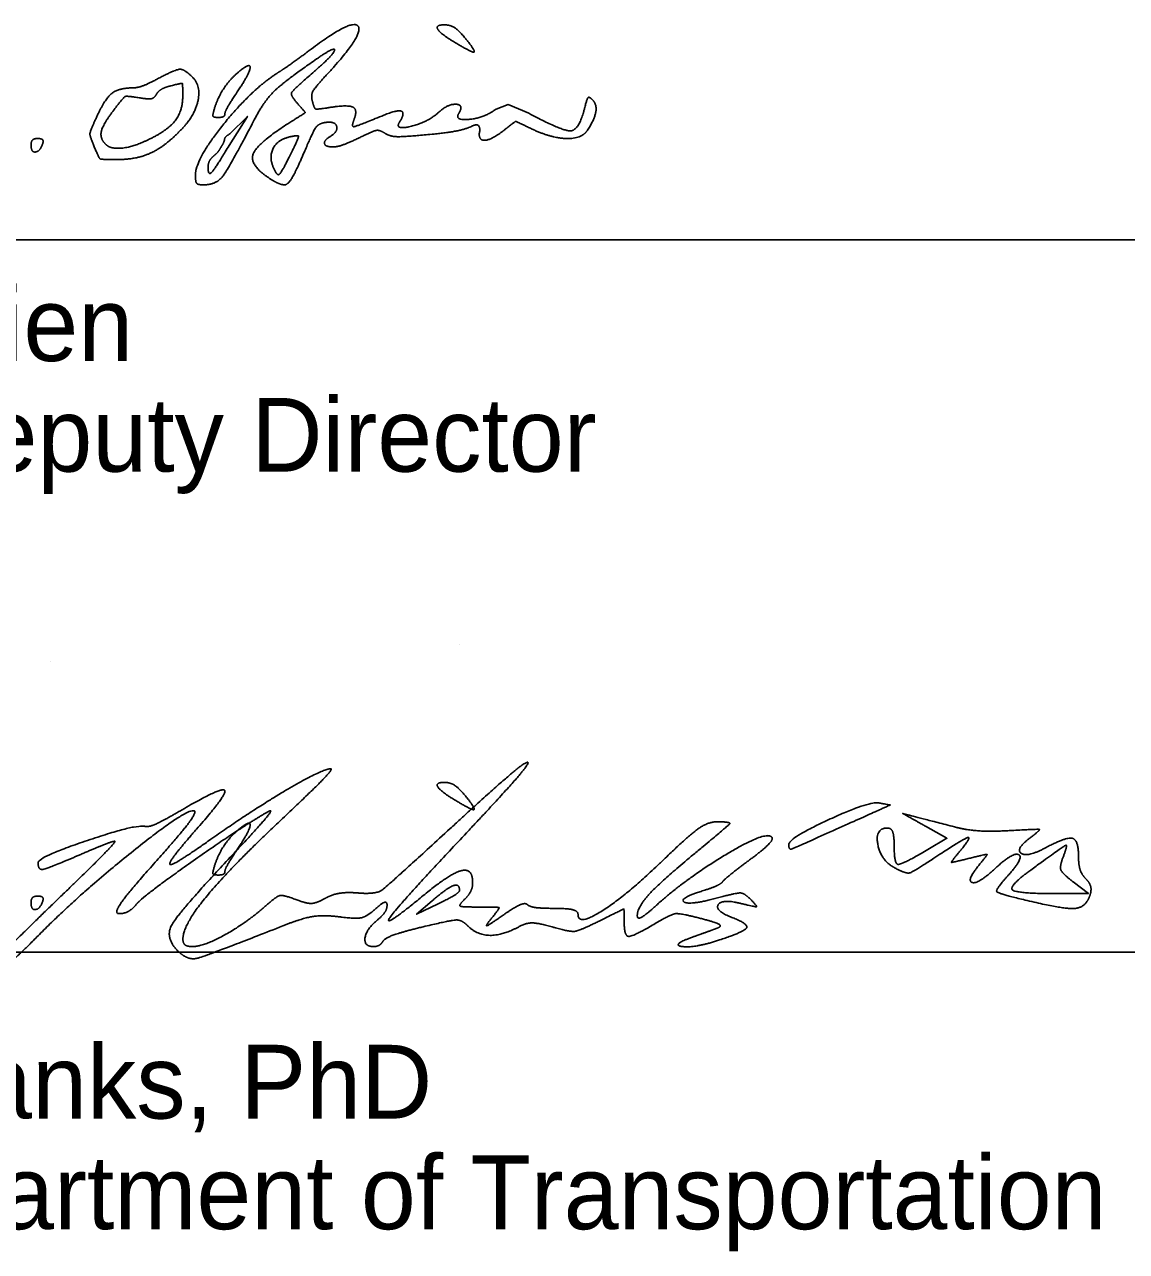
# Model space of a CAD drawing. Extents: x 0 to 34, y 0 to 22.
# Drawn here: x 25.679 to 27.771, y 6.366 to 8.695 of the extents above; entities that cross this region are included whole.
import ezdxf

# ---------------------------------------------------------------- set-up
doc = ezdxf.new("R2010")
doc.units = 0
doc.layers.add('SH_Data', color=7, linetype='Continuous')
doc.layers.add('SH_Text', color=7, linetype='Continuous')

msp = doc.modelspace()

# ---------------------------------------------------------------- linework, layer by layer
at = {"layer": 'SH_Data'}
for p, q in [((24.5279, 8.2866), (28.0279, 8.2866)), ((24.5279, 6.9345), (28.0279, 6.9345))]:
    msp.add_line(p, q, dxfattribs=at)
at = {"layer": 'SH_Text'}
for p, q in [((26.4932, 8.6629), (26.4932, 8.6629)), ((26.5045, 7.5178), (26.5045, 7.5178)), ((25.7273, 7.4868), (25.7273, 7.4868)), ((26.4932, 7.2248), (26.4932, 7.2248)), ((27.1295, 7.1387), (27.1295, 7.1387)), ((27.582, 7.0325), (27.582, 7.0325))]:
    msp.add_line(p, q, dxfattribs=at)
for points in [[(26.636, 8.5269), (26.597, 8.5435), (26.574, 8.535)], [(26.0685, 8.4876), (26.1019, 8.5208), (26.0672, 8.4659)], [(27.3933, 7.1291), (27.4297, 7.1506), (27.3889, 7.1736)], [(27.642, 7.0456), (27.6982, 7.0457), (27.6695, 7.0678)], [(26.4527, 7.032), (26.4232, 7.0064), (26.4638, 7.0261)]]:
    msp.add_lwpolyline(points, dxfattribs=at)
for points in [[(26.2529, 8.6006), (26.3225, 8.6754), (26.3023, 8.7082), (26.2232, 8.6489)], [(26.4932, 8.6629), (26.467, 8.6789), (26.4588, 8.6952), (26.4772, 8.6947)], [(26.4772, 8.6947), (26.4887, 8.6944), (26.5064, 8.6812), (26.5222, 8.661)], [(26.2232, 8.6489), (26.2012, 8.6324), (26.1724, 8.6119), (26.1592, 8.6035)], [(26.2332, 8.63), (26.2688, 8.6547), (26.2661, 8.6386), (26.2292, 8.6066)], [(26.5222, 8.661), (26.5367, 8.6425), (26.5254, 8.6433), (26.4932, 8.6629)], [(26.0861, 8.6061), (26.1081, 8.6243), (26.1061, 8.6024), (26.0827, 8.5674)], [(26.1167, 8.5177), (26.1337, 8.5504), (26.1732, 8.5884), (26.2332, 8.63)], [(25.9977, 8.5954), (25.982, 8.6111), (25.9646, 8.6099), (25.9291, 8.591)], [(25.9786, 8.4983), (26.0029, 8.5241), (26.0137, 8.5794), (25.9977, 8.5954)], [(26.1592, 8.6035), (26.1093, 8.5715), (26.0032, 8.4396), (26.0032, 8.4095)], [(26.0397, 8.537), (26.0462, 8.5577), (26.0692, 8.592), (26.0861, 8.6061)], [(26.2292, 8.6066), (26.1879, 8.5707), (26.1832, 8.5607), (26.1992, 8.543)], [(26.2252, 8.5497), (26.2222, 8.5614), (26.2302, 8.5761), (26.2529, 8.6006)], [(25.883, 8.575), (25.857, 8.575), (25.8307, 8.5532), (25.8153, 8.5191)], [(25.9291, 8.591), (25.9127, 8.5822), (25.892, 8.575), (25.883, 8.575)], [(25.9291, 8.5628), (25.9325, 8.5688), (25.9451, 8.5762), (25.9572, 8.5792)], [(25.9572, 8.5792), (25.9776, 8.5843), (25.9792, 8.5829), (25.9792, 8.5604)], [(25.8483, 8.5331), (25.8668, 8.5573), (25.8727, 8.5602), (25.8962, 8.5564)], [(25.8962, 8.5564), (25.9142, 8.5534), (25.925, 8.5556), (25.9291, 8.5628)], [(25.9792, 8.5604), (25.9792, 8.5309), (25.9497, 8.4937), (25.9121, 8.4759)], [(26.0827, 8.5674), (26.0698, 8.5483), (26.0592, 8.5295), (26.0592, 8.5258)], [(26.2584, 8.5379), (26.2339, 8.534), (26.2289, 8.5358), (26.2252, 8.5497)], [(26.7567, 8.5527), (26.7506, 8.5588), (26.7465, 8.5546), (26.7424, 8.5381)], [(26.7476, 8.495), (26.7612, 8.5159), (26.7656, 8.5438), (26.7567, 8.5527)], [(25.8326, 8.4683), (25.8214, 8.4794), (25.828, 8.5065), (25.8483, 8.5331)], [(26.0467, 8.519), (26.0374, 8.519), (26.0356, 8.5236), (26.0397, 8.537)], [(26.0592, 8.5258), (26.0592, 8.522), (26.0536, 8.519), (26.0467, 8.519)], [(26.1992, 8.543), (26.2118, 8.529), (26.2113, 8.5274), (26.1899, 8.5141)], [(26.3044, 8.5152), (26.3116, 8.5339), (26.2926, 8.5433), (26.2584, 8.5379)], [(26.3905, 8.5099), (26.4015, 8.5275), (26.3872, 8.5341), (26.3611, 8.5234)], [(26.4648, 8.5286), (26.4453, 8.5105), (26.3809, 8.4942), (26.3905, 8.5099)], [(26.5033, 8.527), (26.5134, 8.5434), (26.4821, 8.5447), (26.4648, 8.5286)], [(26.574, 8.535), (26.5525, 8.5185), (26.4941, 8.5122), (26.5033, 8.527)], [(26.7424, 8.5381), (26.7319, 8.4953), (26.7008, 8.492), (26.636, 8.5269)], [(25.8153, 8.5191), (25.8032, 8.4922), (25.8026, 8.4839), (25.8111, 8.4632)], [(26.0178, 8.391), (26.0424, 8.391), (26.0675, 8.4232), (26.1167, 8.5177)], [(26.1899, 8.5141), (26.1224, 8.4722), (26.1042, 8.4293), (26.143, 8.4039)], [(26.208, 8.4491), (26.2265, 8.4924), (26.2371, 8.5076), (26.25, 8.5095)], [(26.25, 8.5095), (26.2679, 8.5122), (26.2747, 8.4925), (26.2592, 8.483)], [(26.3611, 8.5234), (26.3092, 8.5022), (26.2989, 8.5007), (26.3044, 8.5152)], [(26.4563, 8.4875), (26.5084, 8.4924), (26.5469, 8.5119), (26.5419, 8.487)], [(26.59, 8.4954), (26.6104, 8.5115), (26.6116, 8.5115), (26.6411, 8.4975)], [(25.7039, 8.479), (25.6969, 8.479), (25.6912, 8.4733), (25.6912, 8.4663)], [(25.7134, 8.4695), (25.7151, 8.4747), (25.7109, 8.479), (25.7039, 8.479)], [(25.8552, 8.439), (25.8926, 8.439), (25.9478, 8.4655), (25.9786, 8.4983)], [(26.0546, 8.467), (26.0583, 8.4737), (26.059, 8.4825), (26.0685, 8.4876)], [(26.1499, 8.4275), (26.143, 8.4456), (26.1592, 8.476), (26.1786, 8.4811)], [(26.1786, 8.4811), (26.1989, 8.4864), (26.1993, 8.4799), (26.1812, 8.4435)], [(26.2592, 8.483), (26.2466, 8.4751), (26.2499, 8.463), (26.2647, 8.463)], [(26.2647, 8.463), (26.2721, 8.463), (26.2942, 8.4707), (26.3138, 8.4802)], [(26.3138, 8.4802), (26.3413, 8.4935), (26.3526, 8.4955), (26.3634, 8.4887)], [(26.3634, 8.4887), (26.3732, 8.4826), (26.401, 8.4822), (26.4563, 8.4875)], [(26.5419, 8.487), (26.5423, 8.4738), (26.5677, 8.4779), (26.59, 8.4954)], [(26.6411, 8.4975), (26.6784, 8.4797), (26.7368, 8.4783), (26.7476, 8.495)], [(25.6912, 8.4663), (25.6912, 8.4522), (25.7085, 8.4546), (25.7134, 8.4695)], [(25.8111, 8.4632), (25.8201, 8.4416), (25.8248, 8.439), (25.8552, 8.439)], [(25.9121, 8.4759), (25.8843, 8.4627), (25.8422, 8.4587), (25.8326, 8.4683)], [(26.0672, 8.4659), (26.041, 8.422), (26.0272, 8.4076), (26.0272, 8.4243)], [(26.0392, 8.447), (26.0458, 8.4524), (26.0512, 8.4618), (26.0546, 8.467)], [(26.0272, 8.4243), (26.0272, 8.4313), (26.0326, 8.4415), (26.0392, 8.447)], [(26.1812, 8.4435), (26.1659, 8.4127), (26.1573, 8.4083), (26.1499, 8.4275)], [(26.173, 8.3911), (26.1786, 8.3911), (26.1944, 8.4172), (26.208, 8.4491)], [(26.0032, 8.4095), (26.0032, 8.3969), (26.0079, 8.391), (26.0178, 8.391)], [(26.143, 8.4039), (26.1538, 8.3968), (26.1673, 8.391), (26.173, 8.3911)], [(26.4869, 7.1692), (26.5619, 7.2383), (26.6279, 7.2949), (26.6336, 7.295)], [(26.6336, 7.295), (26.6394, 7.2951), (26.5873, 7.2349), (26.518, 7.1613)], [(26.0326, 7.1488), (26.1131, 7.2054), (26.2445, 7.2826), (26.2602, 7.2826)], [(26.2602, 7.2826), (26.265, 7.2826), (26.2237, 7.24), (26.1684, 7.1879)], [(26.4932, 7.2248), (26.467, 7.2408), (26.4588, 7.2571), (26.4772, 7.2567)], [(26.4772, 7.2567), (26.4887, 7.2564), (26.5064, 7.2432), (26.5222, 7.2229)], [(25.9736, 7.2023), (26.0524, 7.2485), (26.0646, 7.2352), (26.0054, 7.1679)], [(26.5222, 7.2229), (26.5367, 7.2045), (26.5254, 7.2052), (26.4932, 7.2248)], [(26.0017, 7.2021), (25.9921, 7.2117), (25.7824, 7.0447), (25.7045, 6.9655)], [(26.142, 7.2016), (26.0929, 7.1738), (25.9046, 7.0416), (25.8914, 7.0257)], [(25.908, 7.1731), (25.9136, 7.1713), (25.9431, 7.1844), (25.9736, 7.2023)], [(25.9239, 7.1017), (25.9702, 7.1534), (26.0052, 7.1986), (26.0017, 7.2021)], [(26.0768, 7.1227), (26.123, 7.1719), (26.1523, 7.2074), (26.142, 7.2016)], [(27.1295, 7.1387), (27.1295, 7.1511), (27.2823, 7.2214), (27.3012, 7.2177)], [(27.3012, 7.2177), (27.3219, 7.2137), (27.3226, 7.2141), (27.201, 7.1595)], [(27.3889, 7.1736), (27.3461, 7.1977), (27.3452, 7.1977), (27.4482, 7.1713)], [(25.7047, 7.1045), (25.7049, 7.1151), (25.8923, 7.1782), (25.908, 7.1731)], [(26.1684, 7.1879), (26.0687, 7.0942), (25.9795, 6.9861), (25.9795, 6.9591)], [(26.0861, 7.168), (26.1081, 7.1862), (26.1061, 7.1643), (26.0827, 7.1294)], [(26.8951, 7.113), (26.9403, 7.1567), (26.9774, 7.1824), (26.9951, 7.1821)], [(26.9951, 7.1821), (27.0194, 7.1816), (27.0156, 7.1752), (26.967, 7.1352)], [(26.0054, 7.1679), (25.9774, 7.1361), (25.9545, 7.1064), (25.9545, 7.102)], [(26.0397, 7.0989), (26.0462, 7.1197), (26.0692, 7.154), (26.0861, 7.168)], [(26.3119, 7.0468), (26.3453, 7.044), (26.3688, 7.0604), (26.4869, 7.1692)], [(26.518, 7.1613), (26.3885, 7.0238), (26.3564, 6.9765), (26.4386, 7.0442)], [(26.8763, 7.0218), (26.93, 7.0706), (27.0769, 7.1606), (27.0938, 7.1549)], [(27.0938, 7.1549), (27.1022, 7.1522), (27.087, 7.1334), (27.0599, 7.1132)], [(27.201, 7.1595), (27.1385, 7.1314), (27.1295, 7.1288), (27.1295, 7.1387)], [(27.3305, 7.0946), (27.304, 7.1088), (27.293, 7.1701), (27.317, 7.1701)], [(27.317, 7.1701), (27.3238, 7.1701), (27.3295, 7.1561), (27.3295, 7.1389)], [(27.4529, 7.1243), (27.4773, 7.1539), (27.4615, 7.1501), (27.4052, 7.1129)], [(27.4482, 7.1713), (27.4688, 7.1661), (27.5138, 7.1633), (27.5482, 7.1652)], [(27.5482, 7.1652), (27.6031, 7.1683), (27.608, 7.1667), (27.5881, 7.1519)], [(27.5881, 7.1519), (27.5593, 7.1304), (27.5822, 7.114), (27.6159, 7.1321)], [(27.6159, 7.1321), (27.6561, 7.1536), (27.6795, 7.1478), (27.6795, 7.1164)], [(25.7273, 7.0207), (25.7983, 7.0891), (25.8537, 7.1451), (25.8502, 7.1451)], [(25.8502, 7.1451), (25.8468, 7.1451), (25.8178, 7.1339), (25.7857, 7.1201)], [(25.9545, 7.102), (25.9545, 7.0975), (25.9896, 7.1186), (26.0326, 7.1488)], [(26.0827, 7.1294), (26.0698, 7.1102), (26.0592, 7.0915), (26.0592, 7.0877)], [(26.967, 7.1352), (26.8929, 7.0743), (26.842, 7.0207), (26.842, 7.004)], [(27.3295, 7.1389), (27.3295, 7.1021), (27.3438, 7.0999), (27.3933, 7.1291)], [(27.6497, 7.1133), (27.6596, 7.1391), (27.6514, 7.136), (27.5888, 7.0904)], [(25.7857, 7.1201), (25.7231, 7.0933), (25.7044, 7.0897), (25.7047, 7.1045)], [(25.9697, 6.937), (25.9445, 6.9623), (25.9734, 7.0124), (26.0768, 7.1227)], [(26.7295, 7.0061), (26.7295, 6.9833), (26.8248, 7.0447), (26.8951, 7.113)], [(27.0599, 7.1132), (27.0328, 7.093), (27.0079, 7.073), (27.0045, 7.0688)], [(27.4052, 7.1129), (27.3652, 7.0864), (27.3519, 7.0831), (27.3305, 7.0946)], [(27.4723, 7.1126), (27.4392, 7.1044), (27.4374, 7.1055), (27.4529, 7.1243)], [(27.4924, 7.1019), (27.507, 7.1195), (27.5047, 7.1207), (27.4723, 7.1126)], [(27.5462, 7.0805), (27.5767, 7.1141), (27.5551, 7.1251), (27.5211, 7.0931)], [(27.6695, 7.0678), (27.6491, 7.0835), (27.6434, 7.0967), (27.6497, 7.1133)], [(27.6795, 7.1164), (27.6795, 7.1006), (27.6858, 7.0813), (27.6936, 7.0735)], [(25.8581, 7.0076), (25.8478, 7.0076), (25.8767, 7.0489), (25.9239, 7.1017)], [(26.0467, 7.0809), (26.0374, 7.0809), (26.0356, 7.0855), (26.0397, 7.0989)], [(26.0592, 7.0877), (26.0592, 7.084), (26.0536, 7.0809), (26.0467, 7.0809)], [(26.4386, 7.0442), (26.487, 7.0841), (26.5295, 7.0945), (26.5295, 7.0664)], [(27.5211, 7.0931), (27.4892, 7.0632), (27.4661, 7.0702), (27.4924, 7.1019)], [(27.582, 7.0325), (27.5272, 7.0454), (27.5215, 7.0531), (27.5462, 7.0805)], [(27.5888, 7.0904), (27.5461, 7.0594), (27.5626, 7.0455), (27.642, 7.0456)], [(26.5045, 7.0517), (26.5045, 7.0652), (26.4804, 7.056), (26.4527, 7.032)], [(26.5295, 7.0664), (26.5295, 7.0575), (26.5227, 7.0434), (26.5145, 7.0351)], [(27.0045, 7.0688), (27.001, 7.0645), (26.9856, 7.0571), (26.9701, 7.0522)], [(27.6936, 7.0735), (27.7014, 7.0657), (27.7044, 7.0505), (27.7003, 7.0397)], [(25.7039, 7.0409), (25.6969, 7.0409), (25.6912, 7.0352), (25.6912, 7.0283)], [(25.7134, 7.0314), (25.7151, 7.0367), (25.7109, 7.0409), (25.7039, 7.0409)], [(26.137, 7.0227), (26.1573, 7.0407), (26.1701, 7.0433), (26.1939, 7.0343)], [(26.1939, 7.0343), (26.2141, 7.0266), (26.2329, 7.0273), (26.2489, 7.0364)], [(26.2489, 7.0364), (26.2623, 7.0439), (26.2906, 7.0486), (26.3119, 7.0468)], [(26.4638, 7.0261), (26.4862, 7.0369), (26.5045, 7.0485), (26.5045, 7.0517)], [(26.5145, 7.0351), (26.5028, 7.0235), (26.5087, 7.0201), (26.541, 7.0201)], [(26.9701, 7.0522), (26.9206, 7.0368), (26.9401, 7.0231), (26.9919, 7.0369)], [(26.9919, 7.0369), (27.0302, 7.0472), (27.0455, 7.0466), (27.0575, 7.0343)], [(27.0575, 7.0343), (27.0702, 7.0214), (27.0666, 7.02), (27.0388, 7.0269)], [(27.7003, 7.0397), (27.6922, 7.0186), (27.651, 7.0161), (27.582, 7.0325)], [(25.617, 6.8958), (25.6067, 6.896), (25.6563, 6.9522), (25.7273, 7.0207)], [(25.6912, 7.0283), (25.6912, 7.0141), (25.7085, 7.0166), (25.7134, 7.0314)], [(25.8914, 7.0257), (25.8831, 7.0157), (25.8682, 7.0076), (25.8581, 7.0076)], [(25.9975, 6.9451), (26.0192, 6.9451), (26.1006, 6.9904), (26.137, 7.0227)], [(26.3444, 7.0161), (26.3287, 7.0019), (26.3075, 6.9975), (26.2749, 7.0017)], [(26.367, 7.0236), (26.367, 7.0307), (26.3568, 7.0273), (26.3444, 7.0161)], [(26.3482, 6.9951), (26.3585, 7.0037), (26.367, 7.0165), (26.367, 7.0236)], [(26.541, 7.0201), (26.5785, 7.0201), (26.5809, 7.0181), (26.5654, 6.9988)], [(26.5871, 7.0046), (26.6085, 7.0196), (26.6293, 7.0287), (26.6332, 7.0248)], [(26.6332, 7.0248), (26.6371, 7.0208), (26.6604, 7.0176), (26.6849, 7.0176)], [(26.6849, 7.0176), (26.7094, 7.0176), (26.7295, 7.0125), (26.7295, 7.0061)], [(26.817, 6.9936), (26.817, 7.0165), (26.8159, 7.0165), (26.7698, 6.9936)], [(26.842, 7.004), (26.842, 6.9965), (26.8574, 7.0045), (26.8763, 7.0218)], [(27.0388, 7.0269), (27.0021, 7.0359), (26.9889, 7.0128), (27.0232, 6.9997)], [(26.2749, 7.0017), (26.2457, 7.0054), (26.2058, 6.9989), (26.1693, 6.9845)], [(26.3412, 6.9451), (26.3229, 6.9451), (26.3274, 6.9779), (26.3482, 6.9951)], [(26.5199, 6.9847), (26.5088, 6.9959), (26.4887, 6.9954), (26.4355, 6.9826)], [(26.5654, 6.9988), (26.5533, 6.9838), (26.5598, 6.9855), (26.5871, 7.0046)], [(26.6807, 6.9823), (26.6538, 6.99), (26.6307, 6.99), (26.6162, 6.9822)], [(26.7698, 6.9936), (26.7324, 6.9751), (26.7138, 6.9728), (26.6807, 6.9823)], [(26.8789, 6.9905), (26.8339, 6.9639), (26.817, 6.9648), (26.817, 6.9936)], [(26.9621, 6.9986), (26.9233, 7.0085), (26.9065, 7.0068), (26.8789, 6.9905)], [(26.992, 6.9794), (27.0034, 6.9835), (26.9917, 6.991), (26.9621, 6.9986)], [(27.0232, 6.9997), (27.0538, 6.9879), (27.0449, 6.973), (26.9981, 6.9576)], [(25.7045, 6.9655), (25.6667, 6.927), (25.6273, 6.8957), (25.617, 6.8958)], [(26.1693, 6.9845), (26.0233, 6.9268), (25.9882, 6.9185), (25.9697, 6.937)], [(26.4355, 6.9826), (26.3972, 6.9734), (26.3629, 6.9612), (26.3594, 6.9555)], [(26.6162, 6.9822), (26.5854, 6.9658), (26.5376, 6.967), (26.5199, 6.9847)], [(26.9482, 6.9636), (26.962, 6.9685), (26.9817, 6.9756), (26.992, 6.9794)], [(25.9795, 6.9591), (25.9795, 6.9514), (25.9876, 6.9451), (25.9975, 6.9451)], [(26.3594, 6.9555), (26.3559, 6.9498), (26.3477, 6.9451), (26.3412, 6.9451)], [(26.9981, 6.9576), (26.9515, 6.9422), (26.9042, 6.9479), (26.9482, 6.9636)]]:
    msp.add_open_spline(points, degree=2, dxfattribs=at)

# ---------------------------------------------------------------- texts
for s, p in [("John W. O'Brien", (24.5279, 8.0566)), ('District  07 Deputy Director', (24.5279, 7.8466)), ('Jack Marchbanks, PhD', (24.5279, 6.6186)), ('Director, Department of Transportation', (24.5279, 6.4086))]:
    msp.add_text(s, height=0.14, dxfattribs=at).set_placement(p)

doc.saveas('drawing.dxf')
